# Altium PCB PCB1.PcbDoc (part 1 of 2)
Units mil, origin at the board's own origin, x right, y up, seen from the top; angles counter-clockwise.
Board outline 1707.5 x 1259.84 mil, 4 copper layers (Top Layer, GND, Sign, Bottom Layer), stack 23.756 mil thick; 63 components, 56 nets, 288 pads, 252 vias.
Unrouted connection lines stored in the file: 1.
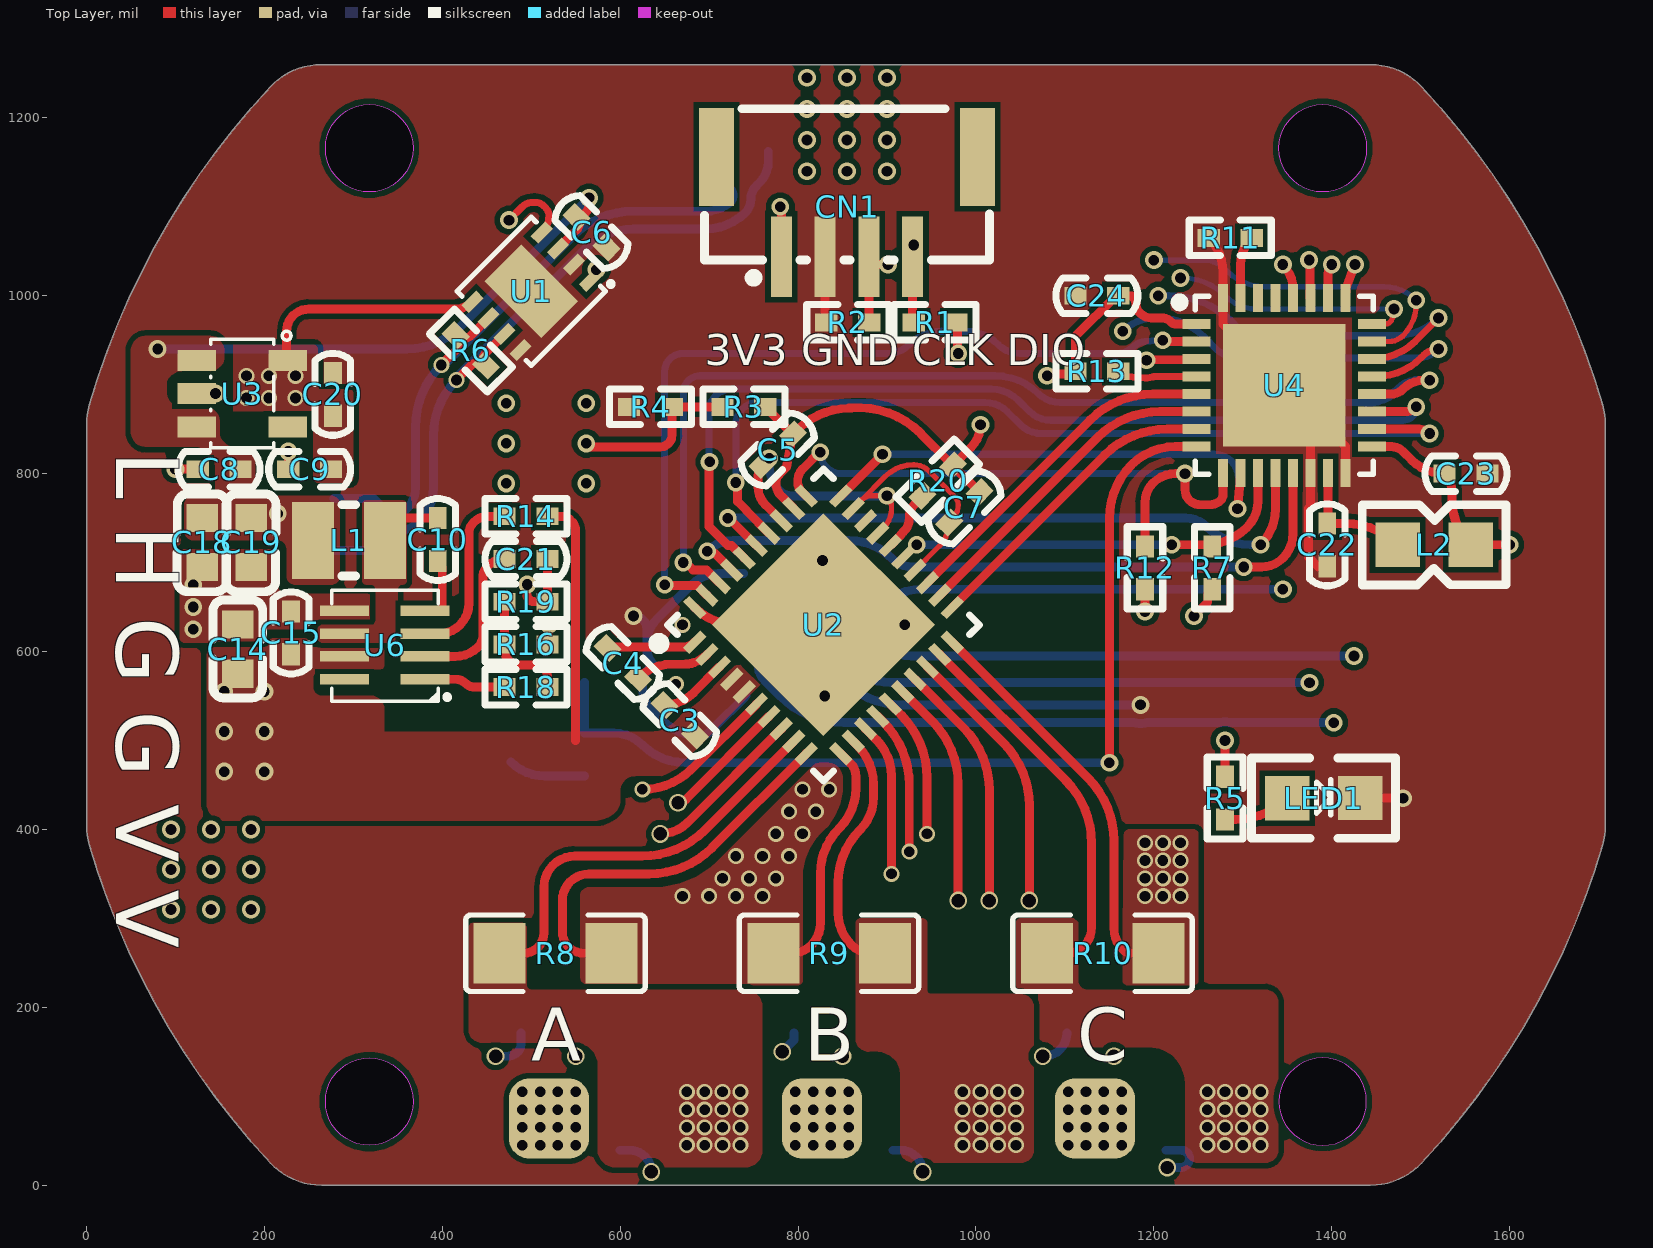
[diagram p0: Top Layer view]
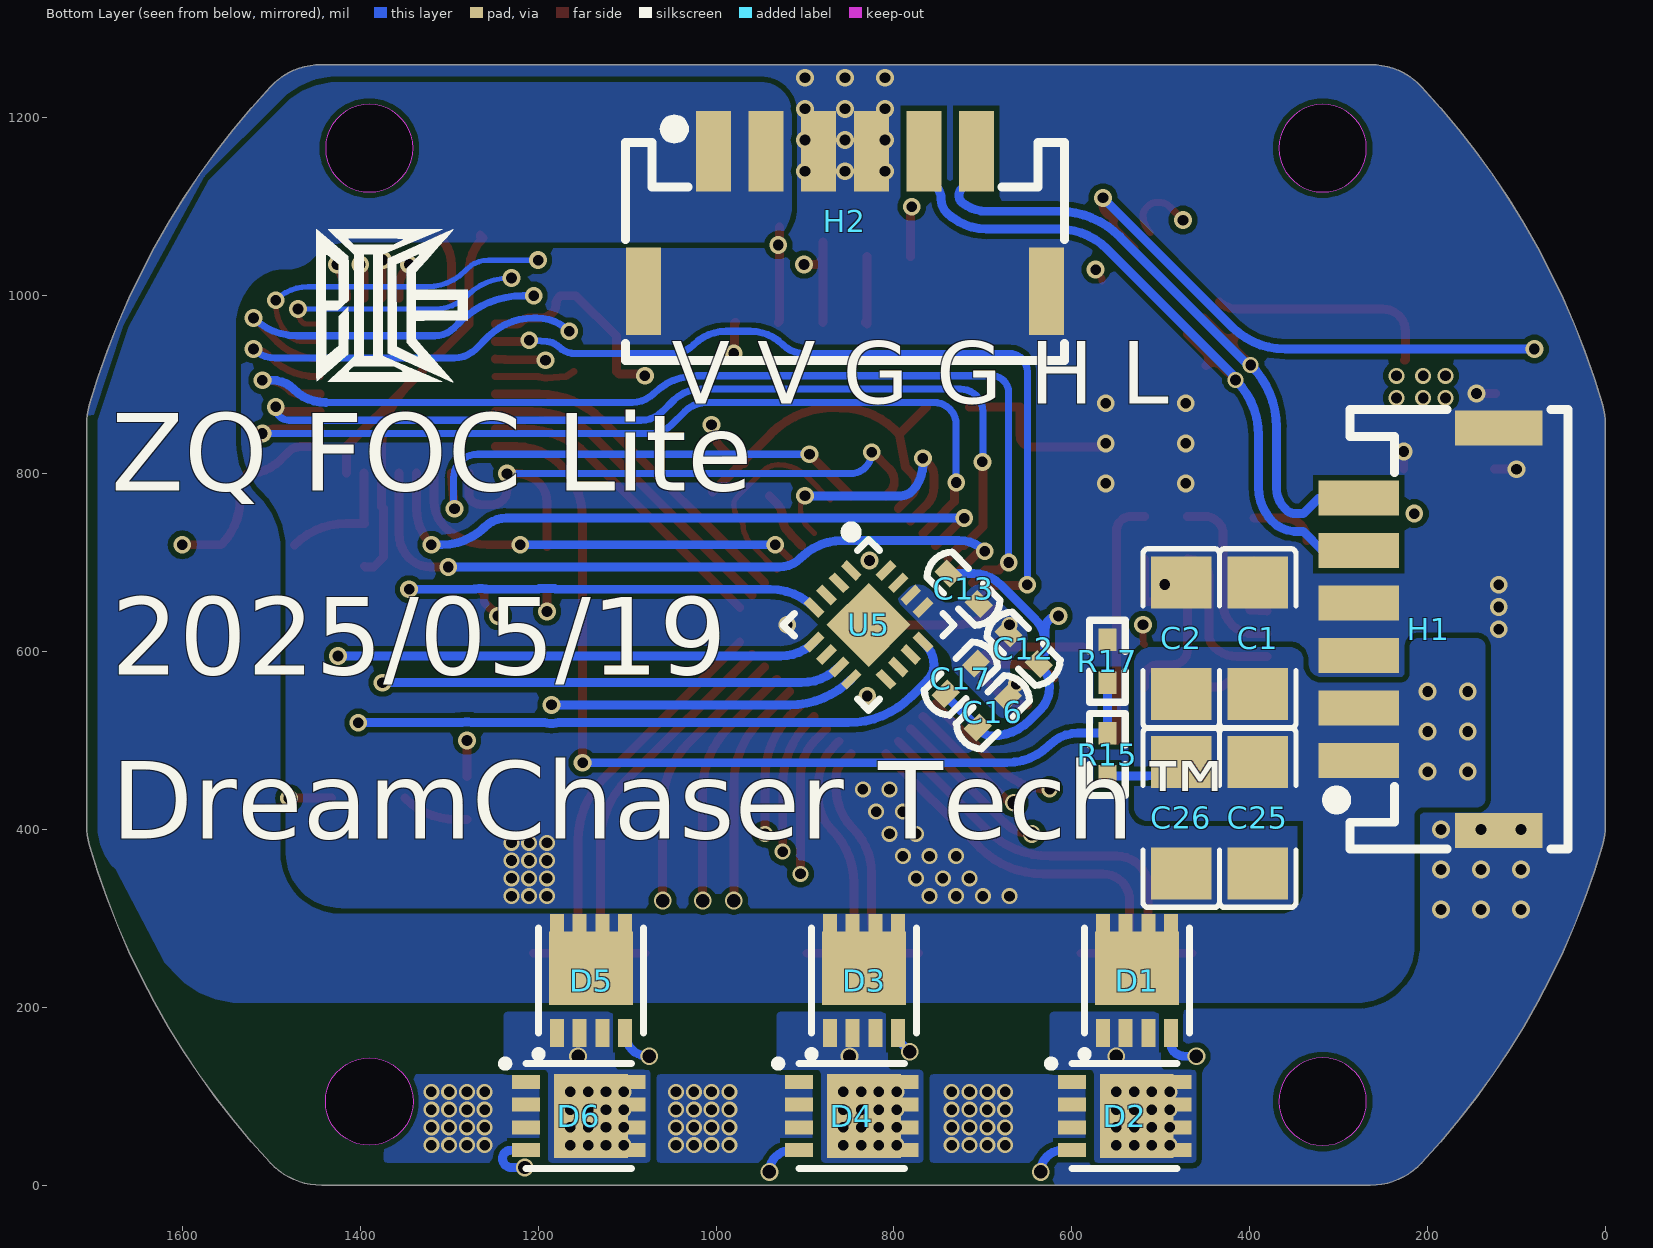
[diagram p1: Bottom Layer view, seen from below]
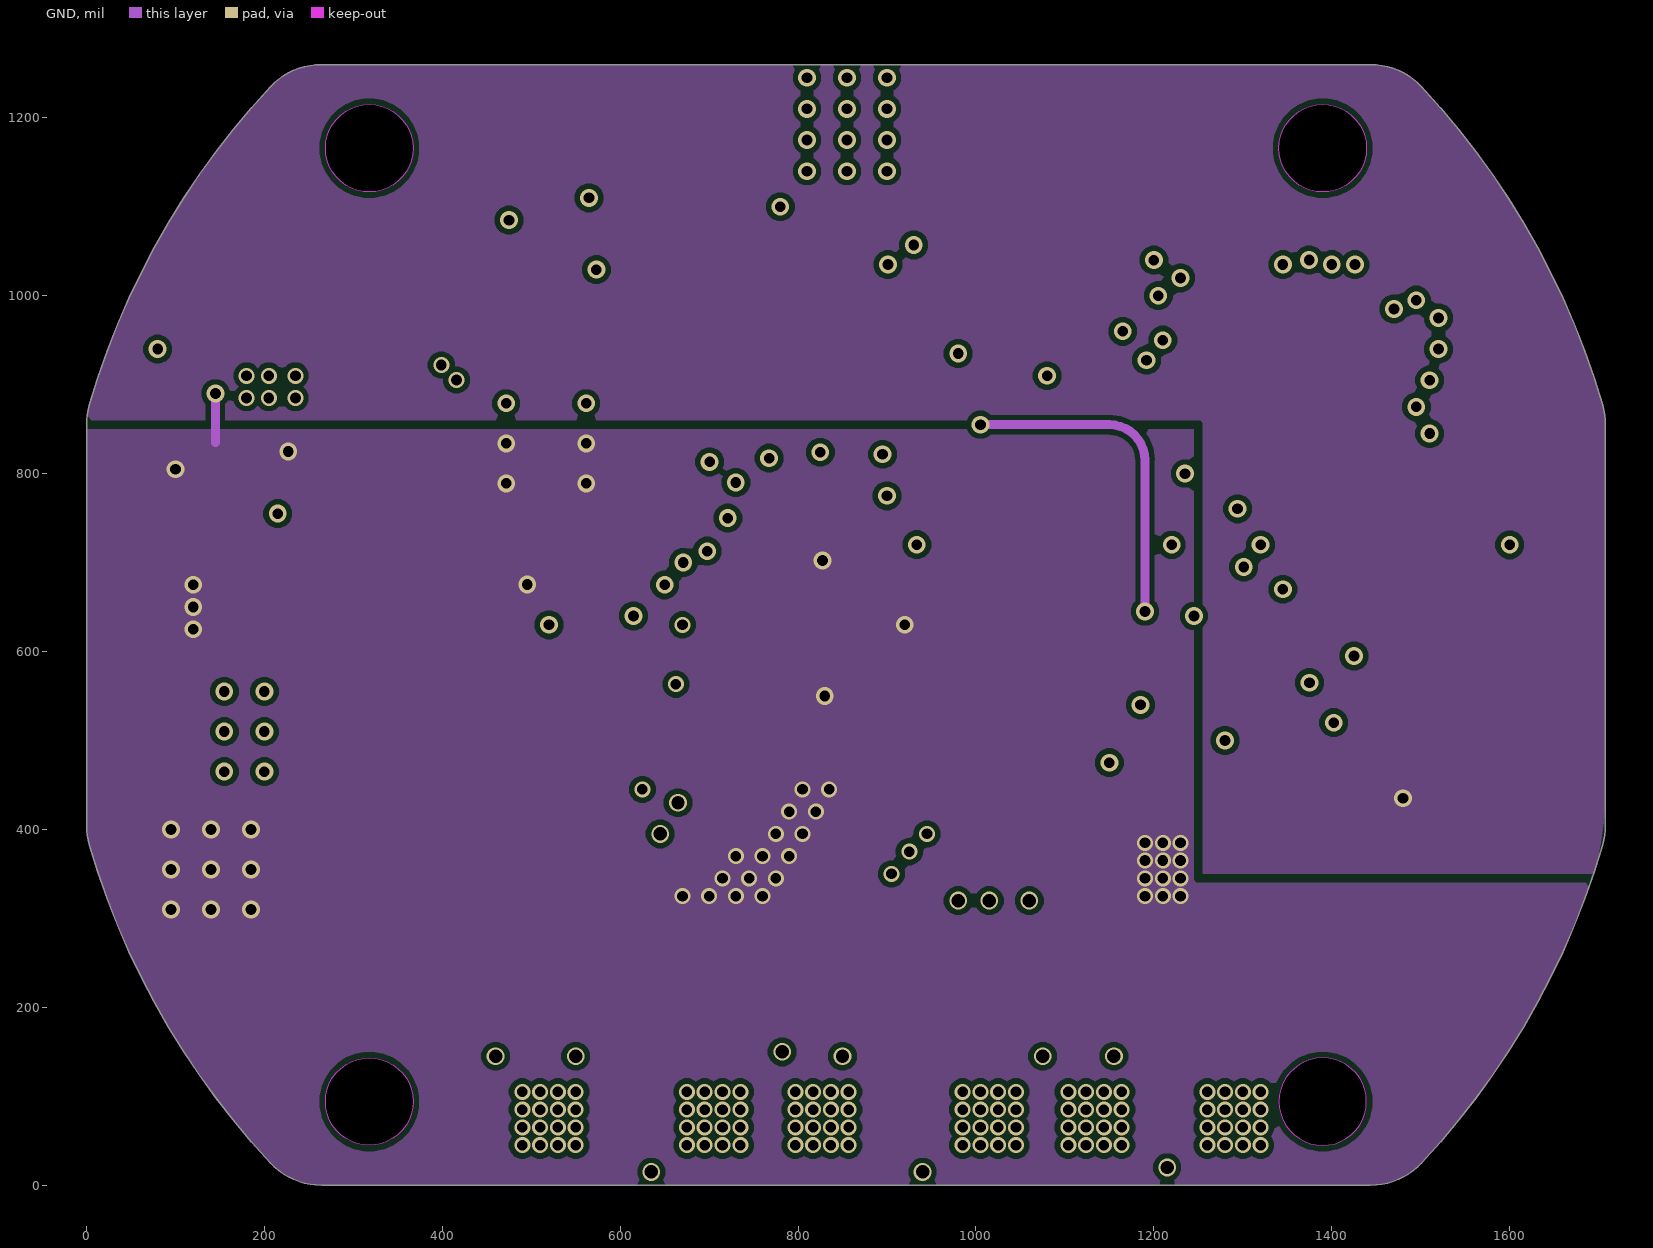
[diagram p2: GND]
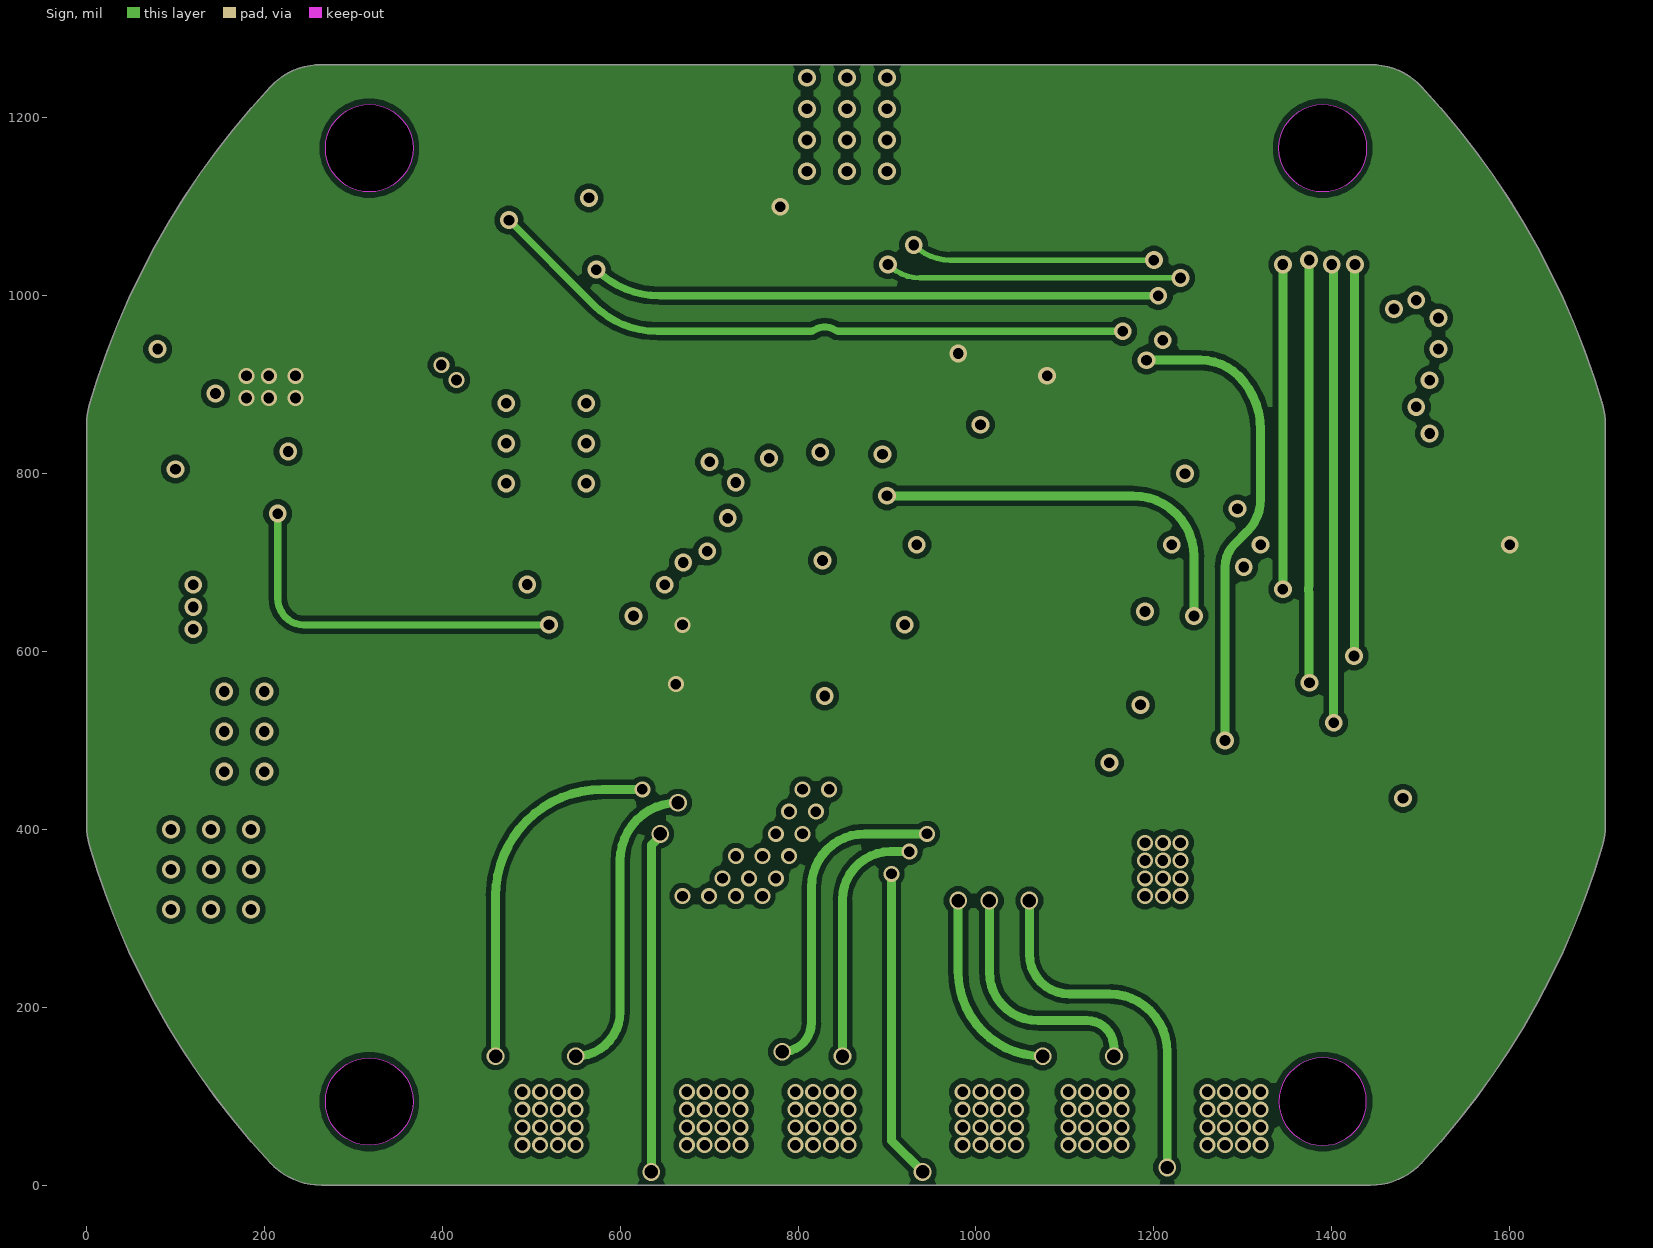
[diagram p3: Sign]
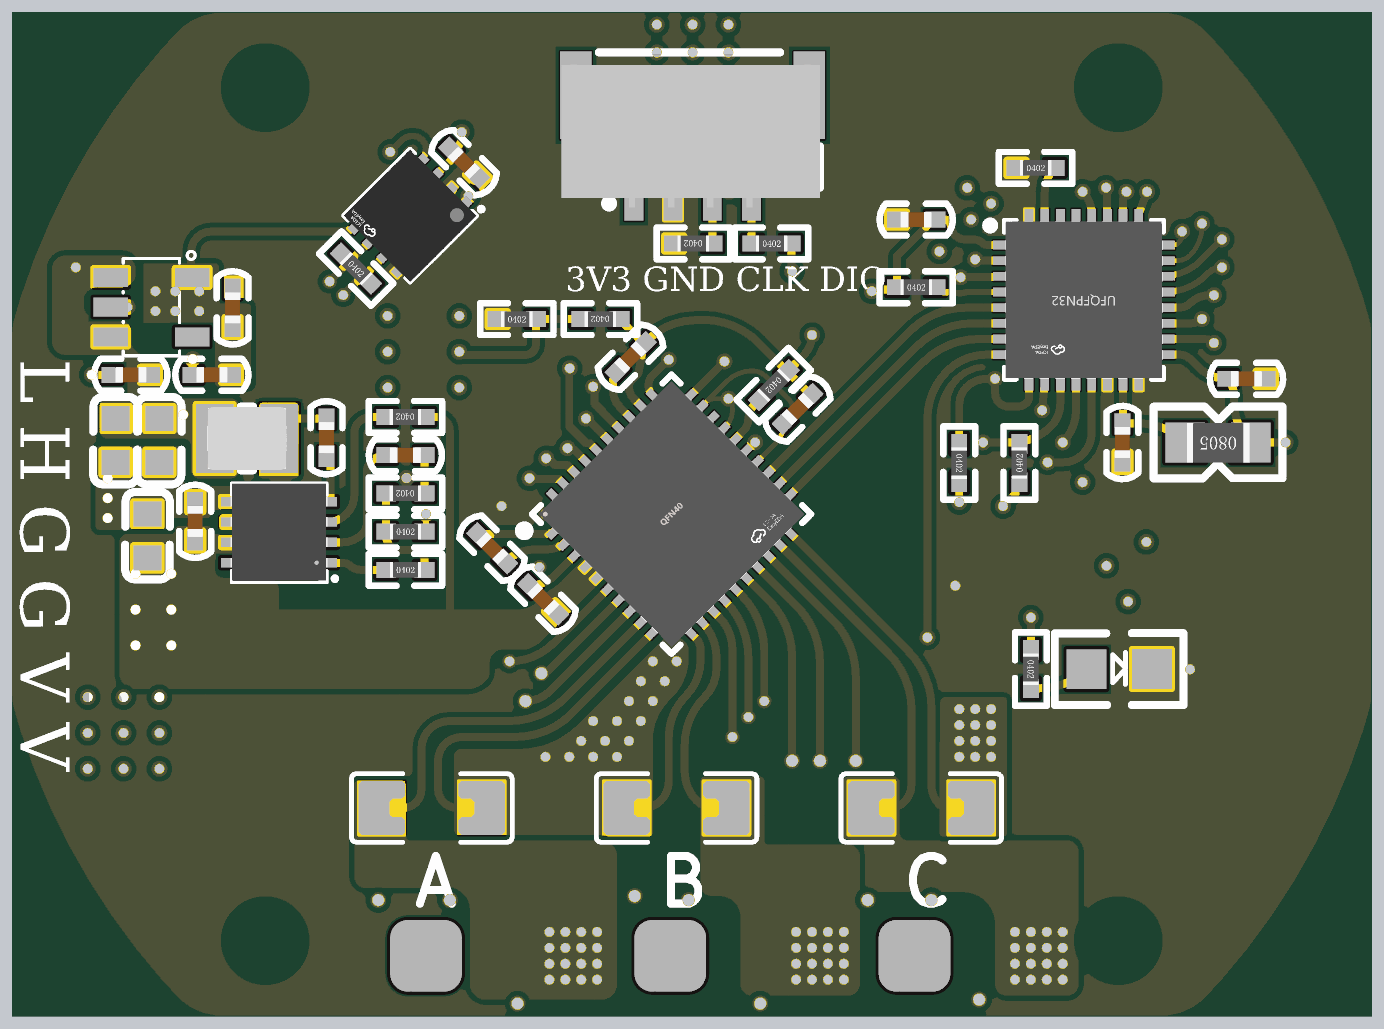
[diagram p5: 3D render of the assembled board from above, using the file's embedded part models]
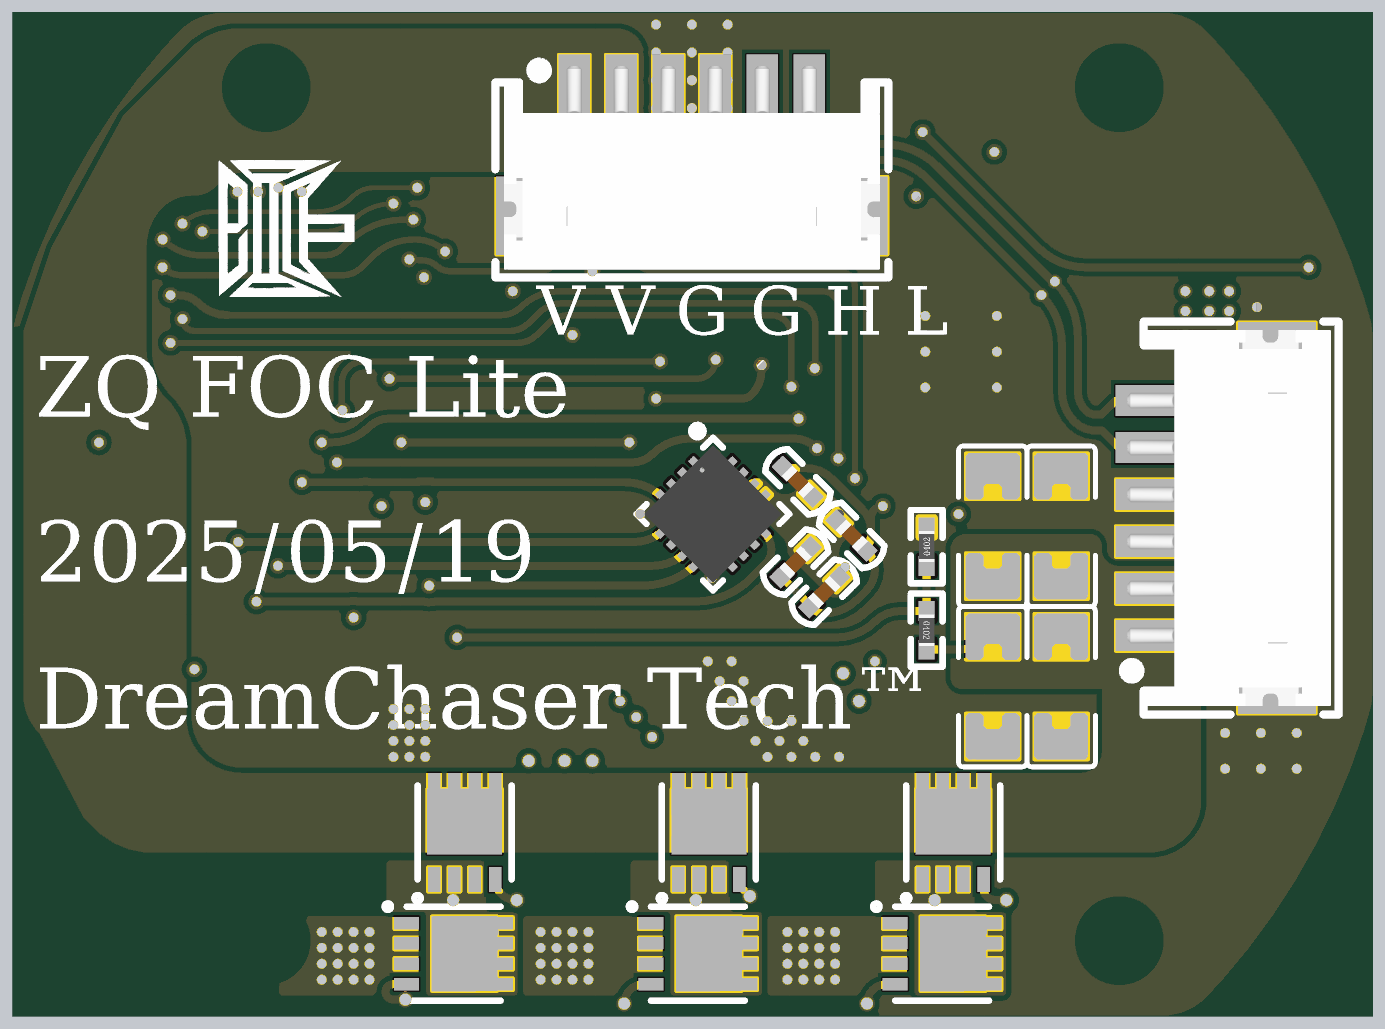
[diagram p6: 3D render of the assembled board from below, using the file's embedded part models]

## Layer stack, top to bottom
Top Solder: solder mask 0.4, Solder Resist, Dk 3.5
Top Layer: signal copper 1.4
Dielectric 2: prepreg 2.8, PP-006, Dk 4.1
GND: signal copper 1.378
Dielectric 1: dielectric 12.6, FR-4, Dk 4.8
Sign: signal copper 1.378
Dielectric 3: prepreg 2.8, PP-006, Dk 4.1
Bottom Layer: signal copper 1.4
Bottom Solder: solder mask 0.4, Solder Resist, Dk 3.5

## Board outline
206.79,24.97 cw(c853.88,629.92) 3.25,382.67 cw(c78.86,404.65) 0.12,404.65 0.13,855.2 cw(c78.87,855.2) 3.25,877.17 cw(c853.88,629.92) 206.79,1234.88 cw(c264.31,1181.1) 264.31,1259.84 1443.44,1259.84 cw(c1443.44,1181.1) 1500.96,1234.88 cw(c853.88,629.92) 1704.5,877.17 cw(c1628.89,855.2) 1707.62,855.2 1707.62,404.65 cw(c1628.89,404.65) 1704.5,382.67 cw(c853.88,629.92) 1500.96,24.97 cw(c1443.44,78.74) 1443.44,0 264.31,0 cw(c264.31,78.74)
cut-out: 1389.77,1116.61 cw(c1389.77,1165.82) 1340.56,1165.82 cw(c1389.77,1165.82) 1389.77,1215.03 cw(c1389.77,1165.82) 1438.99,1165.82 cw(c1389.77,1165.82)
cut-out: 1340.56,94.02 ccw(c1389.77,94.02) 1389.77,44.81 ccw(c1389.77,94.02) 1438.99,94.02 ccw(c1389.77,94.02) 1389.77,143.24 ccw(c1389.77,94.02)
cut-out: 317.98,1116.61 cw(c317.98,1165.82) 268.76,1165.82 cw(c317.98,1165.82) 317.98,1215.03 cw(c317.98,1165.82) 367.19,1165.82 cw(c317.98,1165.82)
cut-out: 317.98,44.81 cw(c317.98,94.02) 268.76,94.02 cw(c317.98,94.02) 317.98,143.24 cw(c317.98,94.02) 367.19,94.02 cw(c317.98,94.02)

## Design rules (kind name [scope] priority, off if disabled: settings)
Clearance [All] p1: gap=6 ignorepadtopadclearanceinfootprint=FALSE except(0: Arc-Hole Track-Hole SMDPad-Hole THPad-Hole Via-Hole Fill-Hole Poly-Hole Region-Hole Text-Hole)
DiffPairsRouting [All] p1: maxlimit=10 minlimit=10 mostfreqgap=10 toplayer_minwidth=8 toplayer_maxwidth=15 toplayer_prefwidth=10 midlayer1_minwidth=8 midlayer1_maxwidth=15 midlayer1_prefwidth=10 midlayer2_minwidth=8 midlayer2_maxwidth=15 midlayer2_prefwidth=10 bottomlayer_minwidth=8 bottomlayer_maxwidth=15 bottomlayer_prefwidth=10 maxuncoupledlength=500
HoleToHoleClearance [All] p1: gap=0 allowstackedmicrovias=TRUE
MinimumSolderMaskSliver [All] p1: minsoldermaskwidth=0
PlaneClearance [All] p1: clearance=6
PlaneConnect [All] p1: planeconnectstyle=Direct reliefexpansion=20 reliefentries=4 reliefconductorwidth=10 reliefairgap=10
PolygonConnect [All] p1: connectstyle=Direct reliefconductorwidth=10 reliefentries=4 polygonreliefangle="90 Angle" airgapwidth=10
RoutingVias [All] p1: holewidth=12 width=18 viastyle="Through Hole" minholewidth=12 minwidth=18 maxholewidth=28 maxwidth=50
SilkToSilkClearance [All] p1: silktosilkclearance=0
SilkToSolderMaskClearance [IsPad] p1: minsilkscreentomaskgap=0 clearancetoexposedcopper=TRUE
SolderMaskExpansion [All] p1: expansion=4 istentingtop=FALSE
SupplyNets "Schematic Supply Nets_6" [InNet('AGND')] p1: voltage=0.000
SupplyNets "Schematic Supply Nets_5" [InNet('PGND')] p2: voltage=0.000
SupplyNets "Schematic Supply Nets_4" [InNet('DGND')] p3: voltage=0.000
SupplyNets "Schematic Supply Nets_3" [InNet('VBUS')] p4: voltage=0.000
SupplyNets "Schematic Supply Nets_2" [InNet('DVDD')] p5: voltage=0.000
SupplyNets "Schematic Supply Nets_1" [InNet('3V3')] p6: voltage=0.000
SupplyNets "Schematic Supply Nets" [InNet('5V')] p7: voltage=0.000
Width [All] p1: maxlimit=20 minlimit=6 preferedwidth=10
23 further rules are at their usual default settings.

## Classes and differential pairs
differential pair CAN: +CAN_P -CAN_N

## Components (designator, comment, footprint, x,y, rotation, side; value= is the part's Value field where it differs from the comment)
C1 "100uF" 1206 374.02,1205.63 r270 bottom
C2 "100uF" 1206 460.02,1205.63 r270 bottom
C3 "1uF" c0402 650,540 r315 top
C4 "47nF" c0402 585.92,604.08 r315 top
C5 "1uF" c0402 794.08,844.08 r225 top
C6 "0.1uF" c0402 584.85,1054.5 r135 top
C7 "0.1uF" c0402 1004.08,779.08 r225 top
C8 "10uF" c0402 125,805 r0 top
C9 "10uF" c0402 226.8,805 r0 top
C10 "100nF" c0402 395,701.8 r90 top
C12 "1uF" C0402 671.26,620.19 r225 bottom
C13 "100nF" C0402 704.68,653.61 r45 bottom
C14 "10uF" C0603 82.05,1217.9 r270 top
C15 "100nF" c0402 230,645 r270 top
C16 "1uF" C0402 705.76,514.69 r135 bottom
C17 "100nF" C0402 741.75,552.52 r135 bottom
C18 "10uF" C0603 217.95,107.22 r90 top
C19 "10uF" C0603 272.95,107.22 r90 top
C20 "0.1uF" c0402 277,865 r90 top
C21 "100nF" c0402 518.2,704 r180 top
C22 "0.1uF" c0402 1395,695.8 r90 top
C23 "0.1uF" c0402 1575,800 r180 top
C24 "0.1uF" c0402 1160,1000 r180 top
C25 "100uF" 1206 407.98,-177.63 r90 bottom
C26 "100uF" 1206 493.98,-177.63 r90 bottom
CN1 "卧式STLINK" CONN-SMD_4P-P1.25_GH1.25-4P 855,1100 r180 top
D1 "NTMFS5C410NL" DFN-8_L3.0-W3.0-P0.65-BL 526.73,230 r180 bottom
D2 "NTMFS5C410NL" DFN-8_L3.0-W3.0-P0.65-BL 540.55,77.72 r270 bottom
D3 "NTMFS5C410NL" DFN-8_L3.0-W3.0-P0.65-BL 833.62,230 r180 bottom
D4 "NTMFS5C410NL" DFN-8_L3.0-W3.0-P0.65-BL 847.44,77.72 r270 bottom
D5 "NTMFS5C410NL" DFN-8_L3.0-W3.0-P0.65-BL 1140.51,230 r180 bottom
D6 "NTMFS5C410NL" DFN-8_L3.0-W3.0-P0.65-BL 1154.33,77.72 r270 bottom
H1 "卧式XH1.5 6PIN" CONN-SMD_6P-P1.50_ZX-ZH1.5-6PWT 180,625 r90 bottom
H2 "卧式XH1.5 6PIN" CONN-SMD_6P-P1.50_ZX-ZH1.5-6PWT 855,1065 r180 bottom
L1 "22uH" IND-SMD_L2.5-W2.0 295,725 r0 top value=10uH
L2 "10μH" L0805 1556.2,720 r180 top
LED1 "LED" led0805 1349.75,435.12 r0 top
R1 "10KΩ" R0402 930,970 r0 top
R2 "10KΩ" R0402 880,970 r180 top
R3 "0Ω" R0402 763.2,875 r180 top
R4 "0Ω" R0402 610,875 r0 top
R5 "2KΩ" R0402 1280,459.32 r270 top
R6 "120Ω" R0402 415.15,955.5 r315 top
R7 "10KΩ" R0402 1265.56,670 r90 top
R8 "30mR" 1206 1118.23,243.81 r180 top
R9 "30mR" 1206 243.87,277.78 r0 top
R10 "30mR" 1206 1733.23,243.81 r180 top
R11 "10KΩ" R0402 1261.8,1065 r0 top
R12 "200KΩ" R0402 1190,718.2 r270 top
R13 "10KΩ" R0402 1111.8,915 r0 top
R14 "10KΩ" R0402 518.2,752 r180 top
R15 "10KΩ" R0402 560,508.2 r270 bottom
R16 "43KΩ" R0402 470,608 r0 top
R17 "1KΩ" R0402 560,565 r90 bottom
R18 "51KΩ" R0402 470,560 r0 top
R19 "8.2KΩ" R0402 518.2,656 r180 top
R20 "0Ω" R0402 974.08,809.08 r225 top
U1 "SIT1057QTK/3" DFN-8_L3.0-W3.0-P0.65-BL-EP 503.14,1007.61 r135 top
U2 "DRV8323HRTAR" QFN-40_L6.0-W6.0-P0.50-BL-EP4.5 828.5,630 r315 top
U3 "XC6201P332MR-HXY" SOT-23-5_L3.0-W1.7-P0.95-LS2.8-BR 175,890 r180 top
U4 "STM32G431KBU3" UFQFPN-32_L5.0-W5.0-P0.50-BL-EP3.5 1346.58,899.21 r270 top
U5 "MA600" qfn-16-l3.0-w3.0-p0.50-tl-ep1.7 828.48,630 r225 bottom
U6 "MP9943" "QFN-8 3x3" 380.55,568.82 r180 top

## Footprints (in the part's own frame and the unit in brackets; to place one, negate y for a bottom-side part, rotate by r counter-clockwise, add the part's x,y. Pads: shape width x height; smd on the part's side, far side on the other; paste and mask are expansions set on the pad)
1206 [mm]
  rect 1.485x1.728 smd paste-100 mask+0.051: 1(13.417,-0.431) 2(16.602,-0.431)
  silkscreen extent 12.45,-1.52 17.57,0.66, body extent 13.41,-1.24 16.61,0.38, height 1.11
c0402 [mil]
  rect 25x20 smd: 1(0,0) 2(48.2,0)
  silkscreen extent -22,-20 70,20, body extent 5,-10 44,10, height 20
C0402 [mil]
  rect 25x20 smd: 1(0,0) 2(48.2,0)
  silkscreen extent -22,-20 70,20, body extent 5,-10 44,10, height 20
C0603 [mm]
  rect 0.8x0.9 smd: 1(14.93,2.234) 2(16.33,2.234)
  silkscreen extent 14.22,1.52 17.02,2.95, body extent 14.82,1.84 16.42,2.64, height 0.78
CONN-SMD_4P-P1.25_GH1.25-4P [mm]
  rect 0.6x2.3 smd mask+0.051: 1(1.875,1.425) 2(0.625,1.425) 3(-0.625,1.425) 4(-1.875,1.425)
  rect 1x2.8 smd mask+0.051: 5(-3.725,-1.425) 6(3.725,-1.425)
  silkscreen extent -4.06,-2.8 4.06,2.16, body extent -4.07,-2.4 4.19,2.15, height 4.13
CONN-SMD_6P-P1.50_ZX-ZH1.5-6PWT [mm]
  rect 1x2.3 smd paste+0 mask+0.05: 1(-3.75,2.473) 2(-2.25,2.473) 3(-0.75,2.473) 4(0.75,2.473) 5(2.25,2.473) 6(3.75,2.473)
  rect 1x2.5 smd paste+0 mask+0.05: 7(5.75,-1.527) 8(-5.75,-1.527)
  silkscreen extent -6.27,-3.5 6.27,3.52, body extent -6,-3.25 6.01,3.25, height 3.78
DFN-8_L3.0-W3.0-P0.65-BL [mm]
  rect 0.4x0.8 smd paste-100 mask+0.051: D(-0.975,1.5) D(-0.325,1.5) D(0.325,1.5) D(0.975,1.5) G(0.975,-1.5) S(-0.975,-1.5) S(-0.325,-1.5) S(0.325,-1.5)
  rect 2.4x2.1 smd paste-100 mask+0.051: D(0,0.35)
  silkscreen extent -1.6,-2.2 1.5,1.5, body extent -1.55,-1.6 1.55,1.6, height 0.8
DFN-8_L3.0-W3.0-P0.65-BL-EP [mm]
  rect 0.3x0.6 smd paste+0 mask+0.05: 1(-0.966,-1.297) 2(-0.316,-1.297) 3(0.334,-1.297) 4(0.984,-1.297) 5(0.984,1.503) 6(0.334,1.503) 7(-0.316,1.503) 8(-0.966,1.503)
  rect 2.3x1.5 smd paste+0 mask+0.05: 9(0.009,0.103)
  silkscreen extent -1.5,-1.7 1.51,1.6, body extent -1.49,-1.4 1.51,1.6, height 1.01
IND-SMD_L2.5-W2.0 [mm]
  rect 1.2x2.2 smd: 1(1.028,0) 2(-1.028,0)
  silkscreen extent -0.2,-1.02 0.2,1.02, body extent -1.26,-1 1.26,1, height 1.2
L0805 [mil]
  rect 50x50 smd: 1(0,0) 2(82.3,0.2)
  silkscreen extent -40,-45 122,45, body extent 1,-24 80,25, height 22
led0805 [mil] "1/8W"
  rect 50x50 smd: 1(0,0) 2(82.3,0.2)
  silkscreen extent -40,-45 122,45, body extent 2,-25 80,25, height 20
"QFN-8 3x3" [mm]
  rect 1.4x0.3 smd: 1(0,0) 2(0,-0.65) 3(0,-1.3) 4(0,-1.95) 5(2.3,-1.95) 6(2.3,-1.3) 7(2.3,-0.65) 8(2.3,0)
  silkscreen extent -0.64,-2.54 2.67,0.64, body extent -0.41,-2.53 2.69,0.57, height 0.94
qfn-16-l3.0-w3.0-p0.50-tl-ep1.7 [mm]
  rect 0.6x0.25 smd: 1(-1.45,0.75) 2(-1.45,0.25) 3(-1.45,-0.25) 4(-1.45,-0.75) 9(1.45,-0.75) 10(1.45,-0.25) 11(1.45,0.25) 12(1.45,0.75)
  rect 0.25x0.6 smd: 5(-0.75,-1.45) 6(-0.25,-1.45) 7(0.25,-1.45) 8(0.75,-1.45) 13(0.75,1.45) 14(0.25,1.45) 15(-0.25,1.45) 16(-0.75,1.45)
  rect 1.7x1.7 smd: 17(0,0)
  silkscreen extent -2.38,-1.72 1.72,1.72, body extent -1.55,-1.55 1.55,1.55, height 0.94
QFN-40_L6.0-W6.0-P0.50-BL-EP4.5 [mm]
  rect 0.25x0.7 smd paste-100 mask+0.051: 1(-2.25,-2.95) 2(-1.75,-2.95) 3(-1.25,-2.95) 4(-0.75,-2.95) 5(-0.25,-2.95) 6(0.25,-2.95) 7(0.75,-2.95) 8(1.25,-2.95) 9(1.75,-2.95) 10(2.25,-2.95) 21(2.25,2.95) 22(1.75,2.95) 23(1.25,2.95) 24(0.75,2.95) 25(0.25,2.95) 26(-0.25,2.95) 27(-0.75,2.95) 28(-1.25,2.95) 29(-1.75,2.95) 30(-2.25,2.95)
  rect 0.7x0.25 smd paste-100 mask+0.051: 11(2.95,-2.25) 12(2.95,-1.75) 13(2.95,-1.25) 14(2.95,-0.75) 15(2.95,-0.25) 16(2.95,0.25) 17(2.95,0.75) 18(2.95,1.25) 19(2.95,1.75) 20(2.95,2.25) 31(-2.95,2.25) 32(-2.95,1.75) 33(-2.95,1.25) 34(-2.95,0.75) 35(-2.95,0.25) 36(-2.95,-0.25) 37(-2.95,-0.75) 38(-2.95,-1.25) 39(-2.95,-1.75) 40(-2.95,-2.25)
  rect 4.5x4.5 smd paste-100 mask+0.051: 41(0,0)
  silkscreen extent -3.15,-3.85 3.15,3.15, body extent -3.01,-3.01 3.01,3.01, height 0.83
R0402 [mil] "1/16W"
  rect 25x20 smd: 1(0,0) 2(48.2,0)
  silkscreen extent -22,-20 70,20, body extent 5,-10 44,10, height 14
SOT-23-5_L3.0-W1.7-P0.95-LS2.8-BR [mm]
  rect 1.1x0.6 smd: 1(1.3,-0.95) 2(1.3,0) 3(1.3,0.95) 4(-1.3,0.95) 5(-1.3,-0.95)
  silkscreen extent -1.4,-1.78 0.9,1.55, body extent -1.5,-1.5 1.5,1.5, height 1.3
UFQFPN-32_L5.0-W5.0-P0.50-BL-EP3.5 [mm]
  rect 0.28x0.8 smd paste-100 mask+0.051: 1(-1.75,-2.5) 2(-1.25,-2.5) 3(-0.75,-2.5) 4(-0.25,-2.5) 5(0.25,-2.5) 6(0.75,-2.5) 7(1.25,-2.5) 8(1.75,-2.5) 17(1.75,2.5) 18(1.25,2.5) 19(0.75,2.5) 20(0.25,2.5) 21(-0.25,2.5) 22(-0.75,2.5) 23(-1.25,2.5) 24(-1.75,2.5)
  rect 0.8x0.28 smd paste-100 mask+0.051: 9(2.5,-1.75) 10(2.5,-1.25) 11(2.5,-0.75) 12(2.5,-0.25) 13(2.5,0.25) 14(2.5,0.75) 15(2.5,1.25) 16(2.5,1.75) 25(-2.5,1.75) 26(-2.5,1.25) 27(-2.5,0.75) 28(-2.5,0.25) 29(-2.5,-0.25) 30(-2.5,-0.75) 31(-2.5,-1.25) 32(-2.5,-1.75)
  rect 3.5x3.5 smd paste-100 mask+0.051: 33(0,0)
  silkscreen extent -2.54,-3.12 2.54,2.54, body extent -2.51,-2.52 2.52,2.51, height 0.61

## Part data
C1 C2 C14 C18 C19 C25 C26: library part 1210贴片电容, "1210贴片电容"
C3 C4 C5 C6 C7 C8 C9 C10 C12 C13 C15 C16 C17 C20 C21 C22 C23 C24: library part 0402贴片电容, "贴片电容0402"
D1 D2 D3 D4 D5 D6: "N沟道MOS管"
L1: library part 0530屏蔽电感, "一体成型屏蔽电感，0530封装，额定电流3A", DC Resistance (DCR)=125mΩ, JLCPCB Part Class="Extended Part", LCSC Part Name="10uH ±20% 3.5A", Manufacturer=XR(祥如), Manufacturer Part=XR0530-100M, Rated Current=3.2A, Saturation Current (Isat)=3.5A, Tolerance=±20%
L2: library part 0805贴片电感, "0805贴片电感"
LED1: library part 0805贴片LED, "0805贴片LED"
R1 R2 R3 R4 R5 R6 R7 R11 R12 R13 R14 R15 R16 R17 R18 R19 R20: library part 0402贴片电阻, "0402贴片电阻"
R8 R9 R10: library part 2512检流电阻, "2512检流电阻"
U2: JLCPCB Part Class="Extended Part", LCSC Part Name="5mA 无刷直流BLDC电机驱动芯片 60V", Manufacturer=TI(德州仪器)
U3: "3.3V LDO", JLCPCB Part Class="Extended Part", Manufacturer="HXY MOSFET(华轩阳电子)", MAX Output Current=300mA, Maximum Input Voltage=12V, Output Voltage=3.3V
U4: JLCPCB Part Class="Extended Part", LCSC Part Name="带DSP和FPU的170MHz主流ARM Cortex-M4 MCU，具有128 KB Flash存储器、数学加速器和中等模拟电平集成", Low Voltage Detection Threshold=1.71V~3.6V, Manufacturer=ST(意法半导体)
U5: "磁编码器"

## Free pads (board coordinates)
  rrect50% 90x90 smd: 2(520,75) 2(826.89,75) 2(1133.78,75)

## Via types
v1: diameter 18, hole 12, Top Layer to Bottom Layer, tented both sides, 138 vias
v2: diameter 20, hole 12, Top Layer to Bottom Layer, tented both sides, 100 vias
v3: diameter 20, hole 15, Top Layer to Bottom Layer, tented both sides, 14 vias

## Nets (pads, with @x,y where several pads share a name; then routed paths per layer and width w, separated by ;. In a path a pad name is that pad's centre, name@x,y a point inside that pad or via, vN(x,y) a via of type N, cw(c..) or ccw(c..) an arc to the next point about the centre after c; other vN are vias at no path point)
3V3: C9.2 C12.1 C13.1 C16.2 C17.2 C20.1 C23.2 C24.1 CN1.1 L2.1 R1.2 R13.1 U1.5 U3.5 U4.1 U4.17 U5.13 U5.14 | length 818.4
  Top Layer w10: U3.5@226.18,927.4 cw(c226.18,928.58) 225,928.58 225,960 cw(c250,960) 250,985 414.16,985 ccw(c414.16,1012.89) U1.5@433.88,993.17 ; v2(780,1100) 781.18,1098.82 CN1.1@781.18,1043.9 ; R1.2@978.2,970 979.1,969.1 979.1,935.9 v2(980,935) ; v2(1080,910) 1081.91,911.91 1108.71,911.91 R13.1@1111.8,915 1111.8,954.3 1157.5,1000 C24.1@1160,1000 1172.93,1000 cw(c1172.93,995) 1176.46,998.54 cw(c1167.93,990) 1180,990 ccw(c1192.07,990) 1183.54,981.46 1185,980 ; 1185,980 ccw(c1197.07,992.07) 1197.07,975 1207.93,975 cw(c1207.93,957.93) 1220,970 ccw(c1224.54,974.54) 1224.54,968.12 U4.1@1248.15,968.12 ; U4.17@1445,830.32 1467.16,830.32 cw(c1467.16,812.16) 1480,825 ; 1480,825 1489.59,815.41 ccw(c1526.8,852.63) C23.2@1526.8,800 cw(c1507,780.2) 1535,780.2 1535,771.18 ccw(c1607.38,771.18) 1556.2,720 v2(1600,720)
  other v1: 662.59,563.3 670,630 180,885 205,885 235,885 180,910 205,910 235,910
5V: C6.2 C8.2 C18.2 C19.2 L1.2 R16.2 U1.3 U3.1 U3.3 | length 1067.2
  Top Layer w8: R16.2@518.2,608 520,609.8 v2(520,630)
  Top Layer w10: U1.3@529.93,1053.02 550.77,1073.87 ccw(c543.41,1081.22) C6.2@550.77,1088.58 ccw(c550.77,1102.81) 565,1102.81 v2(565,1110)
  Sign w8: v2(215,755) 215,659.96 ccw(c245.61,660) 223.98,638.34 ccw(c244.14,658.54) 244.14,630 v2(520,630)
  Bottom Layer w10: v2(80,940) 360,940 ccw(c360,1024.5) 419.75,964.75 v2(565,1110)
AGND: C5.1 C7.1 R3.1 R12.2 R20.1 R20.2 U2.26 U2.32 | length 922
  Top Layer w10: R3.1@763.2,875 794.07,844.13 794.07,844 792.32,835.24 786.91,807.21 778.47,798.47 ccw(c787.07,790) 775,790 ccw(c796.86,790) 781.4,774.54 U2.32@795.1,760.84 ; C5.1@794.21,843.97 cw(c858.63,788.64) 857.09,873.55 859.84,873.77 cw(c867.99,774.97) 938.05,845.12 938.14,845.03 970.26,812.9 R20.1@974.08,809.08 ; U2.26@903.67,719.08 914.59,730 ccw(c907.54,737.09) 915.66,731.26 916.46,732.37 cw(c933.52,720.12) 919.92,736.12 ccw(c913.39,743.7) 922.15,738.87 ccw(c901.85,750) 925,750 cw(c949.14,750) 932.07,767.07 R20.2@940,775 ; C7.1@1004.08,779.08 R20.1@974.08,809.08 ; v2(1005,855) cw(c968.79,855) 994.39,829.39 R20.1@974.08,809.08 ; v2(1190,645) R12.2@1190,670
  GND w10: v2(1005,855) 1150,855 cw(c1150,815) 1190,815 v2(1190,645)
CAN_N: H1.6 H2.6 R6.1 U1.6 | length 829.3
  Top Layer w10: v1(398.95,922.2) 415.15,938.39 ; U1.6@451.98,975.07 432.41,955.5 cw(c423.78,964.13) R6.1@415.15,955.5 ; 415.15,938.39 ccw(c406.59,946.95) R6.1@415.15,955.5 ; 415.15,938.39 ccw(c406.59,946.95) R6.1@415.15,955.5
  Bottom Layer w10: H1.6@278.02,771.98 317.64,771.98 323.02,771.98 340,755 347.93,755 ccw(c347.93,772.07) 360,760 ; 360,760 ccw(c335.86,784.14) 370,784.14 370,852.3 cw(c468.86,852.3) v1(398.95,922.2) ccw(c398.95,929.03) 403.78,924.2 546.01,1066.43 cw(c615,997.43) 615,1095 696.15,1095 ccw(c696.15,1137.97) 723.18,1104.57 ccw(c716.86,1112.32) 726.58,1109.98 ccw(c715.67,1112.59) 726.89,1112.59 ccw(c715.67,1112.59) H2.6@723.61,1120.52 ; H2.6@707.36,1162.36 707.36,1150.58 ccw(c740.7,1150.58) 717.13,1127.01 H2.6@723.6,1120.53
CAN_P: H1.5 H2.5 R6.2 U1.7 | length 876.5
  Top Layer w10: v1(415.93,905.23) 432.12,921.42 ; U1.7@470.07,956.98 449.23,936.13 ; 432.12,921.42 cw(c440.67,912.86) R6.2@449.21,921.44 ; 432.12,921.42 cw(c440.67,912.86) R6.2@449.21,921.44 ; R6.2@449.21,921.44 cw(c456.59,928.78) 449.23,936.13 ; R6.2@449.21,921.44 cw(c456.59,928.78) 449.23,936.13
  Bottom Layer w10: H1.5@277.36,713.58 318.58,713.58 340,735 347.93,735 ccw(c347.93,772.07) 351.5,735.17 ccw(c347.93,772.07) 374.14,745.86 ccw(c335.86,784.14) 390,784.14 390,842.64 cw(c478.51,842.64) 415.93,905.23 cw(c422.75,905.23) 417.93,910.06 560.15,1052.28 cw(c615,997.43) 615,1075 696.15,1075 ccw(c696.15,1137.97) 740.67,1093.44 ccw(c725.67,1108.45) 746.89,1108.45 cw(c768.12,1108.45) 753.11,1123.46 756.66,1127.01 ccw(c733.08,1150.58) 766.42,1150.58 H2.5@766.42,1162.36
DGND: C6.1 C12.2 C13.2 C16.1 C17.1 C20.2 C22.1 C23.1 C24.2 CN1.2 LED1.2 R2.2 R4.1 R11.1 U1.2 U1.8 U1.9 U4.14 U4.16 U4.32 U4.33 U5.8 | length 1432.7
  Top Layer w10: R2.2@830,968.2 cw(c831.8,968.2) R2.2@831.8,970 cw(c835.2,973.4) 830.39,973.4 CN1.2@830.39,1043.9 ; R11.1@1265,1068.2 cw(c1261.8,1068.2) 1261.8,1065 cw(c1223.46,1026.66) 1277.68,1026.66 U4.32@1277.68,997.64 1277.68,968.1 U4.33@1346.57,899.21 U4.33@1346.81,898.97 ; C22.1@1395,695.8 1394.2,695 1385,695 1374,706 1374,761.06 1376.1,763.16 U4.14@1376.1,800.79 1376.1,828.26 ccw(c1276.1,828.26) U4.33@1346.81,898.97 ; U4.16@1415.47,800.79 1415.47,830.31 U4.33@1346.81,898.97 ; LED1.2@1432.05,435.33 1480,435.33 v2(1480,435)
  Bottom Layer w10: v2(615,640) cw(c615,625) 630,625 630,610 ; 680,675 640.61,635.61 ccw(c666.21,610) 630,610 ; 680,675 cw(c710.64,644.36) 710.64,687.69 C13.2@738.76,687.69 ; C17.1@741.75,552.52 cw(c737.32,552.52) 740.46,549.4 C16.1@705.76,514.69 700.36,509.29 cw(c690,519.64) 690,505 cw(c690,565.36) 647.32,522.68 635.61,534.39 cw(c661.21,560) 625,560 cw(c658.64,560) 634.85,583.79 C12.2@637.18,586.11 cw(c654.5,603.43) 630,603.43 630,610 ; U5.8@847.97,568.75 ccw(c917.38,638.16) 917.38,540 v2(1185,540)
DRV8323_CAL: R12.1 U2.31 U4.9 | length 699.5
  Top Layer w10: 805,805 824,824 v2(825,824) ; 805,805 ccw(c818.45,791.66) 802.84,780.94 U2.31@809.01,774.76 ; R12.1@1190,718.2 1190,767.9 cw(c1220.38,767.9) 1198.9,789.38 cw(c1224.54,763.74) 1224.54,800 v2(1235,800) 1235,782.07 ccw(c1252.07,782.07) 1240,770 ccw(c1252.07,782.07) 1252.07,765 1262.93,765 ccw(c1262.93,782.07) 1275,770 ccw(c1268.55,776.45) 1277.67,776.45 U4.9@1277.67,800.79
  Bottom Layer w8: v2(825,824) ccw(c849,824) 849,800 v2(1235,800)
DRV8323_EN: U2.30 U4.10 | length 557.3
  Top Layer w10: U2.30@847.99,774.76 v2(895,821.77) ; v2(1294.09,760.43) 1296.85,790.04 U4.10@1297.36,800.79
  Bottom Layer w8: v2(895,821.77) 1268.23,821.77 cw(c1268.23,795) 1295,795 1295,761.34 cw(c1294.09,761.34) v2(1294.09,760.43)
DRV8323_HA: U2.34 U4.18 | length 1009.5
  Top Layer w10: v2(730,790) 731.91,788.09 731.91,768.79 742,758.7 742,758.26 U2.34@767.26,733.01 ; U4.18@1445,850 1497.93,850 cw(c1497.93,832.93) v2(1510,845)
  Bottom Layer w8: v2(730,790) 730,855 cw(c755,855) 755,880 1010,880 cw(c1010,843.79) 1035.61,869.39 1050,855 ccw(c1074.14,879.14) 1074.14,845 v2(1510,845)
DRV8323_HB: U2.36 U4.19 | length 1064.9
  Top Layer w10: v2(700.55,813.19) 700,812.63 700,740.3 721.3,719 725.48,719 739.31,705.17 U2.36@739.42,705.17 ; U4.19@1445,869.69 1482.18,869.69 ccw(c1482.18,887.82) v2@1495,875
  Bottom Layer w8: v2(700.55,813.19) 700,813.19 700,870 cw(c725,870) 725,895 1017.28,895 cw(c1017.28,852.22) 1047.53,882.47 1060,870 ccw(c1084.14,894.14) 1084.14,860 1480,860 ccw(c1480,875) v2(1495,875)
DRV8323_HC: U2.38 U4.20 | length 1174.7
  Top Layer w10: v2(671,700) 673.71,700 681.91,691.8 697,691.8 711.47,677.33 U2.38@711.58,677.33 ; U4.20@1445,889.37 1466.41,889.37 ccw(c1466.41,908.59) 1480,895 ; 1480,895 cw(c1504.14,870.86) 1504.14,905 v2(1510,905)
  Bottom Layer w8: v2(671,700) 671,891 cw(c690,891) 690,910 1021.72,910 cw(c1021.72,841.72) 1070,890 ccw(c1094.14,914.14) 1094.14,880 1438.79,880
  Bottom Layer w10: 1438.79,880 ccw(c1438.79,931.21) 1475,895 ; 1475,895 cw(c1499.14,870.86) 1499.14,905 v2(1510,905)
DRV8323_LA: U2.35 U4.12 | length 737.4
  Top Layer w10: v2(721,750) 722.31,750 753.23,719.08 U2.35@753.34,719.08 ; v2@1320,720 ccw(c1279.61,760.39) 1336.73,760.39 U4.12@1336.73,800.79
  Bottom Layer w10: v2(721,750) 1235.86,750 cw(c1235.86,715.86) 1260,740 ccw(c1308.28,788.28) 1308.28,720 v2(1320,720)
DRV8323_LB: U2.37 U4.13 | length 799.2
  Top Layer w10: v2(697.8,712.8) 699.72,710.89 705.74,710.89 725.39,691.24 U2.37@725.5,691.24 ; v2(1301,695) 1320.86,695 ccw(c1320.86,729.14) 1345,705 ccw(c1317.45,732.55) 1356.41,732.55 U4.13@1356.41,800.79
  Bottom Layer w10: v2@699.6,714.6 v2(697.8,712.8) cw(c727.25,683.35) 727.25,725 856.72,725 cw(c856.72,656.72) 905,705 ccw(c929.14,729.14) 929.14,695 v2(1301,695)
DRV8323_LC: U2.39 U4.2 | length 919.4
  Top Layer w10: v2(650,675) 651,674 686.95,674 697.55,663.41 U2.39@697.66,663.41 ; v2(1210,950) ccw(c1213.79,953.79) 1213.79,948.43 U4.2@1248.15,948.43
  Bottom Layer w8: v2(650,675) 650,915 cw(c670,915) 670,935 900.86,935 ccw(c900.86,969.14) 925,945 ; 925,945 cw(c961.21,908.79) 961.21,960 988.79,960 cw(c988.79,908.79) 1025,945 ; 1025,945 ccw(c1049.14,969.14) 1049.14,935 1158.63,935 ccw(c1158.63,960.13) 1176.39,942.36 ccw(c1165,960) 1178.01,943.51 1178.64,944.01 cw(c1191.65,927.53) 1190.04,948.47 v2(1210,950)
DRV8323_nF: R7.2 U2.25 U4.11 | length 463
  Top Layer w8: U2.25@917.59,705.17 918.07,705.17 933.03,720.12 v2(933.52,720.12)
  Top Layer w10: v2(1220,720) 1256.65,720 1256.72,720 ccw(c1256.72,788.28) 1305,740 ccw(c1275.93,769.07) 1317.04,769.07 U4.11@1317.04,800.79
  Bottom Layer w8: v2(933.52,720.12) v2@933.58,720.06
  Bottom Layer w10: v2@933.58,720.06 1219.94,720.06 v2(1220,720)
DRV8323_SOA: U2.23 U4.5 | length 386.3
  Top Layer w10: U2.23@945.43,677.33 1128.19,860.09 cw(c1198.9,789.38) 1198.9,889.38 U4.5@1248.15,889.38
DRV8323_SOB: U2.22 U4.6 | length 369.9
  Top Layer w10: U2.22@959.35,663.41 1136.34,840.4 cw(c1207.05,769.69) 1207.05,869.69 U4.6@1248.15,869.69
DRV8323_SOC: U2.21 U4.7 | length 353.6
  Top Layer w10: U2.21@973.27,649.49 1144.5,820.72 cw(c1215.21,750.01) 1215.21,850.01 U4.7@1248.15,850.01
DVDD: C5.2 C7.2 R7.1 U2.24 U2.27 U2.29 U2.33 | length 1037
  Top Layer w6: U2.27@889.75,733.01 896.7,739.96 ccw(c876.65,760) 905,760 905,762.93 ccw(c887.93,762.93) v2(900,775) 882.24,775 ccw(c882.24,760.09) 871.7,770.63 897.68,796.61 cw(c930,764.29) 930,810 cw(c930,785.86) 947.07,802.93 976.46,773.54 cw(c967.93,765) 980,765 cw(c955.86,765) 972.93,747.93 C7.2@970,745 cw(c933.15,745) 959.21,718.94 U2.24@931.51,691.24
  Top Layer w10: 755,785 ccw(c783.74,785) 763.42,764.68 U2.33@781.18,746.92 ; C5.2@755,797.93 cw(c772.07,797.93) C5.2@760,810 ; 755,785 C5.2@755,797.93 ; v2@1245,640 1260.56,655.56 1260.56,665 R7.1@1265.56,670
  Sign w10: v2(900,775) 1176.72,775 cw(c1176.72,706.72) 1225,755 cw(c1176.72,706.72) 1245,706.72 v2(1245,640)
  Bottom Layer w10: v2(767.47,817.31) 767.47,810.25 ccw(c810.25,810.25) 780,780 ccw(c792.07,792.07) 792.07,775 v2(900,775)
ENCODER_CLK: U4.26 U5.12 | length 1258.2
  Top Layer w10: U4.26@1395.79,997.64 1395.79,1024.84 cw(c1410.16,1024.84) v2@1400,1035
  Sign w10: v2@1400,1035 cw(c1394.83,1029.83) 1402.14,1029.83 v2(1402.14,520)
  Bottom Layer w10: U5.12@767.24,610.51 764.39,607.67 ccw(c787.05,585) 755,585 ccw(c779.14,585) 762.07,567.93 780.71,549.29 ccw(c851.42,620) 851.42,520 1177.19,520 cw(c1177.19,510) 1179.7,519.68 ccw(c1185,540) 1190.31,519.68 cw(c1192.81,510) 1192.81,520 1272.19,520 ccw(c1272.19,530) 1274.7,520.32 cw(c1280,500) 1285.31,520.32 ccw(c1287.81,530) 1287.81,520 v2(1402.14,520)
  other v2: 1400,1035
ENCODER_CS: U4.25 U5.5 | length 1019
  Top Layer w10: U4.25@1415.47,997.64 1415.98,1008.39 v2(1426,1035)
  Sign w10: v2(1425,595) 1425.5,595.5 1425.5,1034.5 v2(1426,1035)
  Bottom Layer w10: U5.5@889.74,610.51 ccw(c927.18,647.96) 927.18,595 v2(1425,595)
ENCODER_MISO: U4.27 U5.7 | length 1036.2
  Top Layer w10: v2(1374.5,1040.1) 1375.59,1039.02 1375.59,998.15 U4.27@1376.1,997.64
  Sign w10: v2(1374.5,1040.1) 1374.5,675.57 cw(c1364.5,675.57) 1374.34,673.79 ccw(c1395,670) 1374.34,666.22 cw(c1364.5,664.43) 1374.5,664.43 1374.5,566.2 ccw(c1376.2,566.2) v2@1375,565
  Bottom Layer w10: U5.7@861.89,582.67 ccw(c904.56,625.34) 904.56,565 v2(1375,565)
ENCODER_MOSI: U4.28 U5.4 | length 867.2
  Top Layer w10: v2@1345,1035 cw(c1317.43,1007.43) 1356.42,1007.43 U4.28@1356.42,997.64
  Sign w10: v2(1345,670) v2(1345,1035)
  Bottom Layer w10: U5.4@889.74,649.49 cw(c939.26,599.97) 939.26,670 1180.3,670 1181.3,671 1198.7,671 1199.7,670 1257.19,670 ccw(c1257.19,680) 1259.7,670.32 cw(c1265,650) 1270.31,670.32 ccw(c1272.81,680) 1272.81,670 v2(1345,670)
FDCAN_RX: U1.4 U4.21 | length 1280.8
  Top Layer w8: v2(475,1085) 490,1100 ; 490,1100 cw(c502.07,1087.93) 502.07,1105 505,1105 cw(c505,1092.93) 513.54,1101.46 516.46,1098.54 cw(c507.93,1090) 520,1090 cw(c494.13,1090) 512.42,1071.71 U1.4@511.83,1071.12 ; U4.21@1445,909.06 1449.45,909.06 ccw(c1449.45,980.55) 1500,930 ; 1500,930 1502.93,932.93 cw(c1520,915.86) v2(1520,940)
  Sign w8: v2(475,1085) 570.71,989.29 ccw(c641.42,1060) 641.42,960 814.03,960 ccw(c814.03,968) 818.58,961.42 cw(c830,945) 841.41,961.42 ccw(c845.97,968) 845.97,960 v2(1165,960)
  Bottom Layer w8: v2@1165,960 cw(c1201.21,923.79) 1201.21,975 1205,975 cw(c1205,902.57) 1256.21,953.79 1270,940 ccw(c1294.14,964.14) 1294.14,930 1495.86,930 ccw(c1495.86,964.14) v2(1520,940)
FDCAN_TX: U1.1 U4.22 | length 1079.6
  Top Layer w8: U1.1@566.12,1016.83 566.12,1019.53 573.23,1026.64 v2(573.23,1029.35) ; U4.22@1445,928.74 ccw(c1445,998.12) 1494.06,949.06 v2(1520,975)
  Sign w8: v2(573.23,1029.35) 573.29,1029.29 ccw(c644,1100) 644,1000 v2(1205,1000)
  Bottom Layer w8: v2(1205,1000) 1216.86,1000 cw(c1216.86,900) 1287.57,970.71 1294.14,964.14 ccw(c1316.21,986.21) 1316.21,955 1471.72,955 ccw(c1471.72,1023.28) v2(1520,975)
NetC3_1: C3.1 U2.3 | length 77.3
  Top Layer w10: C3.1@650,540 ccw(c650,585.65) 682.28,553.37 U2.3@711.58,582.67
NetC4_1: C4.1 U2.1 | length 99.5
  Top Layer w10: C4.1@585.92,604.08 cw(c588.13,601.87) 588.13,605 670.42,605 ccw(c670.42,623.84) U2.1@683.74,610.52
NetC4_2: C4.2 U2.2 | length 84.8
  Top Layer w10: C4.2@620,570 cw(c657.79,532.21) 657.79,585.65 671.25,585.65 ccw(c671.25,623.01) 676.81,586.07 679.11,586.42 ccw(c677.47,597.29) 680.99,586.87 683.2,587.62 ccw(c671.25,623.01) U2.2@697.66,596.59
NetC10_1: C10.1 U6.4 | length 76.3
  Top Layer w10: U6.4@380.55,645.59 400,646.5 400,694.3 C10.1@395,701.8
NetC10_2: C10.2 L1.1 U6.6 | length 73.8
  Top Layer w10: L1.1@335.48,725 cw(c360.48,725) 360.48,750 C10.2@395,750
